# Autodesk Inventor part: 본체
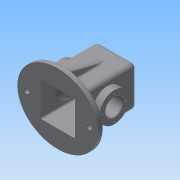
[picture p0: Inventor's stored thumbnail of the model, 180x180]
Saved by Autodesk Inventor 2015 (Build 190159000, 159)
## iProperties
Created: 2017-07
Part Number: 본체
Material: 일반
Document SubType Name: Modeling
Designer: Administrator
Density: 1 g/cm^3
Appearance: 기본값
Author: Administrator
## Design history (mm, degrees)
sketch "스케치1"
  geometry: L1 (75, 65)-(-75, 65); L2 (-75, 65)-(-75, -65); L3 (-75, -65)-(75, -65); L4 (75, -65)-(75, 65); L5 (75, 65)-(-75, -65); L6 (-75, 65)-(75, -65); 2 further points; 1 other entity
  constraints: 12 end point, 3 horizontal, 2 midpoint, 2 parallel, 1 coincident, 1 perpendicular, 1 vertical, 2 other
  dimensions: "d0" = 75 horizontal distance of point (0, 0) L2.end; "d1" = 65 vertical distance of point (0, 0) L2.end
extrude "돌출1" new body sketch "스케치1" distance "d3" = 10; taper "d4" = 0 deg
sketch "스케치2"
  geometry: L1 (-37, -37)-(37, -37); L2 (37, -37)-(37, 37); L3 (37, 37)-(-37, 37); L4 (-37, 37)-(-37, -37); L5 (-37, -37)-(37, 37); L6 (37, -37)-(-37, 37); 1 further point
  constraints: 12 end point, 2 midpoint, 2 parallel, 1 horizontal, 1 perpendicular
  dimensions: "d5" = 74 distance of L1.start L1.end; "d6" = 74 distance of L1.end L2.end
extrude "돌출2" join sketch "스케치2" distance "d7" = 100; taper "d8" = 0 deg
sketch "스케치3"
  geometry: L1 (-37, 10)-(37, 10) reference; L2 (-37, 10)-(-37, 110) reference; L3 (37, 110)-(-37, 110) reference; L4 (37, 10)-(37, 110) reference; L5 (37, 110)-(-37, 110) reference; L6 (0, 110)-(0, 120); L7 (0, 120)-(20, 120); L8 (0, 110)-(20.875, 110); L9 (20, 120)-(20.875, 110); L10 (20.875, 110)-(20.875, 115.228); L11 (0, 120)-(-20, 120); L12 (0, 110)-(-20.875, 110); L13 (-20, 120)-(-20.875, 110); L14 (-20.875, 110)-(-20.875, 115.228); 1 further point
  constraints: 18 end point, 3 symmetric about line, 2 vertical, 1 collinear, 1 horizontal, 1 midpoint, 1 point on line
  dimensions: "d9" = 10 distance of L6.start L6.end; "d10" = 20 distance of L6.end L7.end; "d11" = 5 deg angle of L9 L10
extrude "돌출3" join sketch "스케치3" stored distance "d12" = 40; taper "d13" = 0 deg
sketch "스케치4"
  geometry: L1 (-28, -10)-(102, -10) reference; C1 r 27.5 at (37, 45); 1 further point
  constraints: 1 centre point, 1 vertical alignment
  dimensions: "d14" = 55 distance from line of L1 C1.centre; "d15" = 55 diameter of C1
extrude "돌출4" join sketch "스케치4" distance "d16" = 13; taper "d17" = 0 deg
node "작업 평면1"
sketch "스케치5"
  geometry: L1 (-32, 32)-(32, 32); L2 (32, 32)-(32, -32); L3 (32, -32)-(-32, -32); L4 (-32, -32)-(-32, 32); L5 (-32, 32)-(32, -32); L6 (32, 32)-(-32, -32); 1 further point
  constraints: 12 end point, 2 midpoint, 2 parallel, 1 horizontal, 1 perpendicular
  dimensions: "d18" = 64 distance of L2.end L3.end; "d19" = 64 distance of L3.end L1.start
extrude "돌출5" cut sketch "스케치5" distance "d20" = 105; taper "d21" = 0 deg
sketch "스케치6"
  geometry: L1 (-50, 82.5)-(-50, 27.5) reference; L2 (-37, 27.5)-(-37, 82.5) reference; L3 (-37, 27.5)-(-50, 27.5) reference; L4 (-37, 82.5)-(-50, 82.5) reference; L5 (-37, 82.5)-(-32, 82.5); L6 (-25, 75.5)-(-25, 55); L7 (-32, 0)-(-32, 105) reference; L8 (-32, 82.5)-(-25, 75.5); L9 (-32, 55)-(-25, 55); L10 (-32, 82.5)-(-32, 55); 1 further point
  constraints: 10 end point, 2 horizontal, 2 point on line, 1 collinear, 1 perpendicular
  dimensions: "d23" = 135 deg angle of L7 L8; "d24" = 7 distance from line of L7 L6.start; "d25" = 20.5 distance of L6.start L6.end
revolve "회전1" sketch "스케치6" stored, may be unused: angle "d26" = 90 deg
sketch "스케치7"
  geometry: C1 r 16 at (0, 0); C2 r 20.5 at (0, 0) reference; 1 further point
  constraints: 1 centre point, 1 concentric
  dimensions: "d27" = 32 diameter of C1
extrude "돌출6" cut sketch "스케치7" stored distance "d28" = 105; taper "d29" = 0 deg
chamfer "모따기1" distance "d30" = 1; stored, may be unused: second distance "d31" = 2, angle "d32" = 45 deg
sketch "스케치8"
  geometry: C1 r 17 at (0, 0) reference; 2 further points
  constraints: 1 horizontal alignment
  dimensions: "d33" = 22.5 distance of point (22.5, 0) C1.centre
hole "구멍1" sketch "스케치8" at (22.5, 0) diameter "d34" = 3.459; stored, may be unused: countersink angle "d38" = 90 deg, drill point angle "d40" = 118 deg; dims "d35" = 8, "d36" = 4, "d37" = 2, "d39" = 10
fillet "모깎기1" dims "d44" = 0.5
fillet "모깎기2" dims "d45" = 8
fillet "모깎기3" dims "d46" = 3
fillet "모깎기4" dims "d47" = 0.5
sketch "스케치9"
  geometry: L1 (102, 0)-(-28, 0) reference; L2 (-18, 0)-(0, 72.194); L3 (-28, 0)-(-28, -10); L4 (0, 0)-(0, 92) reference; L5 (-18, 0)-(0, 0); L6 (0, 72.194)-(0, 0); 1 further point
  constraints: 8 end point, 2 point on line, 1 horizontal, 1 perpendicular, 1 vertical
  dimensions: "d48" = 10 distance of L1.end L2.start; "d49" = 14 deg angle of L3 L2
extrude "돌출7" join sketch "스케치9" stored distance "d50" = 10; taper "d51" = 0 deg
node "작업 평면2"
fillet "모깎기7" dims "d54" = 3
fillet "모깎기8" dims "d55" = 3
fillet "모깎기9" dims "d62" = 3
fillet "모깎기10" dims "d63" = 3
sketch "스케치13"
  geometry: C1 r 14 at (17.251, 17); 1 further point
  constraints: 1 centre point, 1 coincident
  dimensions: "d64" = 28 diameter of C1
extrude "돌출10" cut sketch "스케치13" distance "d65" = 4; taper "d66" = 0 deg
sketch "스케치14"
  geometry: C1 r 10.5 at (0, 0); 1 further point
  constraints: 1 centre point, 1 coincident
  dimensions: "d67" = 21 diameter of C1
extrude "돌출11" cut sketch "스케치14" distance "d68" = 20; taper "d69" = 0 deg
sketch "스케치15"
  geometry: C1 r 5 at (-58, 0); 1 further point
  constraints: 1 centre point, 1 horizontal alignment
  dimensions: "d70" = 58 distance of point (0, 0) C1.centre; "d71" = 10 diameter of C1
extrude "돌출12" cut sketch "스케치15" stored distance "d72" = 20; taper "d73" = 0 deg
fillet "모깎기11" dims "d74" = 3
fillet "모깎기12" dims "d75" = 3
node "솔리드1"
mirror "대칭1"
mirror "대칭2"
pattern_circular "원형 패턴1" dims angle "d42" = 360 deg
mirror "대칭3"
mirror "대칭4"
mirror "대칭5"
mirror "대칭6"
node "투영된 루프1"
node "투영된 루프2"
